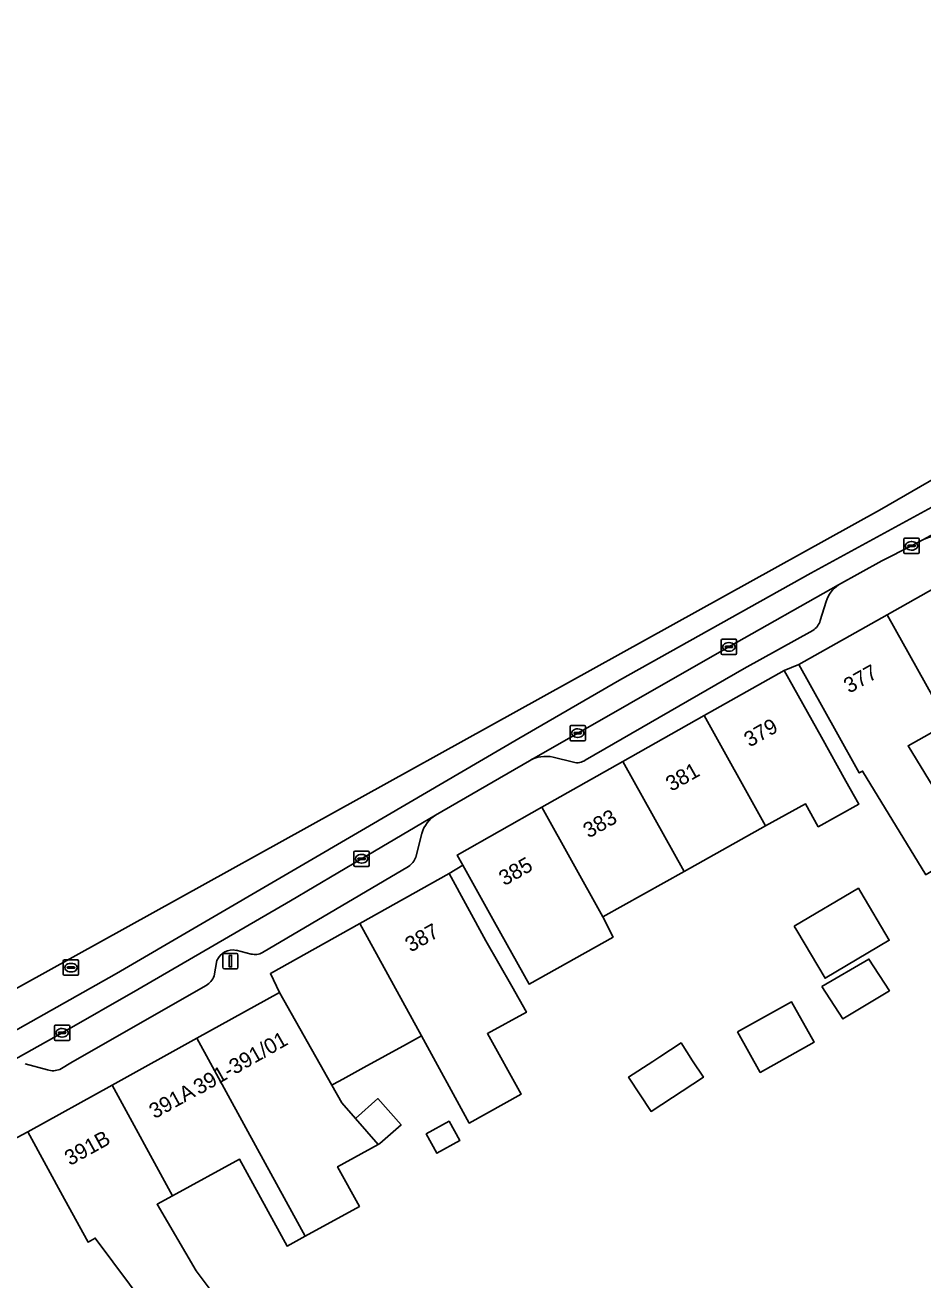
# Model space of a CAD drawing. Extents: x 159817 to 160765, y 380688 to 381638.
# Drawn here: x 159875.5 to 159934.1, y 381436.1 to 381517.9 of the extents above; entities that cross this region are included whole.
import ezdxf

# ---------------------------------------------------------------- set-up
doc = ezdxf.new("R2010")
doc.units = 0
for name, color, linetype in [('IMGEO_Erf', 7, 'Continuous'), ('IMGEO_Kolk', 7, 'Continuous'), ('IMGEO_Lichtmast', 7, 'Continuous'), ('IMGEO_Pand', 7, 'Continuous'), ('IMGEO_Pand_nummerreeks', 7, 'Continuous'), ('IMGEO_Parkeervlak_open', 7, 'Continuous'), ('IMGEO_Rijbaan_lokaal_gesloten', 7, 'Continuous'), ('IMGEO_Rijbaan_lokaal_open', 7, 'Continuous'), ('IMGEO_Rioolput', 7, 'Continuous'), ('IMGEO_Voetpad_open', 7, 'Continuous')]:
    doc.layers.add(name, color=color, linetype=linetype)

msp = doc.modelspace()

# ---------------------------------------------------------------- linework, layer by layer
at = {"layer": 'IMGEO_Erf'}
for points in [[(159934.277, 381462.493), (159930.15, 381469.253), (159929.941, 381469.137), (159928.43, 381471.845), (159925.993, 381476.211), (159925.038, 381475.821), (159927.474, 381471.455), (159929.066, 381468.602), (159929.907, 381467.095), (159927.269, 381465.623), (159926.428, 381467.131), (159923.828, 381465.68), (159918.523, 381462.72), (159913.217, 381459.76), (159913.881, 381458.44), (159908.411, 381455.371), (159906.154, 381459.409), (159904.083, 381463.121), (159903.194, 381462.581), (159905.596, 381458.196), (159907.276, 381455.227), (159908.233, 381453.535), (159905.691, 381452.141), (159907.884, 381448.189), (159904.501, 381446.311), (159901.386, 381451.995), (159900.403, 381451.456), (159897.624, 381449.931), (159896.26, 381449.183), (159895.648, 381448.847), (159895.545, 381448.79), (159896.202, 381447.623), (159897.083, 381446.618), (159898.555, 381447.908), (159900.065, 381446.186), (159898.679, 381444.97), (159898.574, 381444.917), (159895.925, 381443.466), (159897.344, 381440.876), (159893.815, 381438.943), (159892.623, 381438.29), (159889.516, 381443.961), (159885.161, 381441.575), (159884.154, 381441.024), (159886.707, 381436.69), (159891.258, 381430.588)], [(159935.718, 381472.36), (159933.119, 381470.91), (159937.177, 381464.264)], [(159888.044, 381428.191), (159880.12, 381438.814), (159879.651, 381438.557), (159878.123, 381441.346), (159875.721, 381445.731), (159871.093, 381443.281), (159870.548, 381444.237), (159851.506, 381433.392)]]:
    msp.add_lwpolyline(points, dxfattribs=at)
for points in [[(159925.701, 381459.139), (159929.887, 381461.622), (159930.046, 381461.353), (159931.898, 381458.231), (159927.713, 381455.748), (159925.861, 381458.87)], [(159927.501, 381455.219), (159930.567, 381456.998), (159931.907, 381454.941), (159928.877, 381453.102)], [(159921.997, 381452.255), (159925.51, 381454.222), (159926.992, 381451.576), (159923.479, 381449.609)], [(159916.361, 381447.069), (159914.901, 381449.308), (159916.475, 381450.334), (159916.926, 381450.628), (159918.317, 381451.535), (159919.071, 381450.379), (159919.777, 381449.297)], [(159902.399, 381444.344), (159901.7, 381445.604), (159903.192, 381446.432), (159903.891, 381445.172)]]:
    msp.add_lwpolyline(points, close=True, dxfattribs=at)
at = {"layer": 'IMGEO_Kolk'}
for p, q in [((159932.844, 381483.51), (159932.844, 381484.362)), ((159932.919, 381484.436), (159933.771, 381484.436)), ((159933.146, 381483.979), (159933.544, 381483.979)), ((159933.332, 381484.216), (159933.357, 381484.216)), ((159933.845, 381484.362), (159933.845, 381483.51)), ((159933.771, 381483.436), (159932.919, 381483.436)), ((159933.103, 381483.93), (159933.103, 381483.942)), ((159933.541, 381483.893), (159933.143, 381483.893)), ((159933.355, 381483.656), (159933.33, 381483.656)), ((159933.587, 381483.942), (159933.587, 381483.93)), ((159920.935, 381476.921), (159920.935, 381477.773)), ((159921.01, 381477.847), (159921.862, 381477.847)), ((159921.423, 381477.627), (159921.448, 381477.627)), ((159921.936, 381477.773), (159921.936, 381476.921)), ((159921.862, 381476.847), (159921.01, 381476.847)), ((159921.194, 381477.341), (159921.194, 381477.353)), ((159921.632, 381477.304), (159921.234, 381477.304)), ((159921.237, 381477.39), (159921.635, 381477.39)), ((159921.446, 381477.067), (159921.421, 381477.067)), ((159921.678, 381477.353), (159921.678, 381477.341)), ((159911.082, 381471.302), (159911.082, 381472.154)), ((159911.157, 381472.228), (159912.009, 381472.228)), ((159911.341, 381471.722), (159911.341, 381471.734)), ((159911.384, 381471.771), (159911.782, 381471.771)), ((159911.57, 381472.008), (159911.595, 381472.008)), ((159911.825, 381471.734), (159911.825, 381471.722)), ((159912.083, 381472.154), (159912.083, 381471.302)), ((159912.009, 381471.228), (159911.157, 381471.228)), ((159911.779, 381471.685), (159911.381, 381471.685)), ((159911.593, 381471.448), (159911.568, 381471.448)), ((159896.987, 381463.116), (159896.987, 381463.968)), ((159897.062, 381464.042), (159897.914, 381464.042)), ((159897.246, 381463.536), (159897.246, 381463.548)), ((159897.289, 381463.585), (159897.687, 381463.585)), ((159897.475, 381463.822), (159897.5, 381463.822)), ((159897.73, 381463.548), (159897.73, 381463.536)), ((159897.988, 381463.968), (159897.988, 381463.116)), ((159897.914, 381463.042), (159897.062, 381463.042)), ((159897.684, 381463.499), (159897.286, 381463.499)), ((159897.498, 381463.262), (159897.473, 381463.262)), ((159877.457, 381451.769), (159877.457, 381452.621)), ((159877.532, 381452.695), (159878.384, 381452.695)), ((159877.716, 381452.189), (159877.716, 381452.201)), ((159878.154, 381452.152), (159877.756, 381452.152)), ((159877.759, 381452.238), (159878.157, 381452.238)), ((159877.945, 381452.475), (159877.97, 381452.475)), ((159878.2, 381452.201), (159878.2, 381452.189)), ((159878.458, 381452.621), (159878.458, 381451.769)), ((159878.384, 381451.695), (159877.532, 381451.695)), ((159877.968, 381451.915), (159877.943, 381451.915))]:
    msp.add_line(p, q, dxfattribs=at)
for points in [[(159932.844, 381483.51), (159932.844, 381484.362)], [(159932.919, 381484.436), (159933.771, 381484.436)], [(159933.845, 381484.362), (159933.845, 381483.51)], [(159933.771, 381483.436), (159932.919, 381483.436)], [(159920.935, 381476.921), (159920.935, 381477.773)], [(159921.01, 381477.847), (159921.862, 381477.847)], [(159921.936, 381477.773), (159921.936, 381476.921)], [(159921.862, 381476.847), (159921.01, 381476.847)], [(159911.082, 381471.302), (159911.082, 381472.154)], [(159911.157, 381472.228), (159912.009, 381472.228)], [(159912.083, 381472.154), (159912.083, 381471.302)], [(159912.009, 381471.228), (159911.157, 381471.228)], [(159896.987, 381463.116), (159896.987, 381463.968)], [(159897.062, 381464.042), (159897.914, 381464.042)], [(159897.988, 381463.968), (159897.988, 381463.116)], [(159897.914, 381463.042), (159897.062, 381463.042)], [(159877.457, 381451.769), (159877.457, 381452.621)], [(159877.532, 381452.695), (159878.384, 381452.695)], [(159878.458, 381452.621), (159878.458, 381451.769)], [(159878.384, 381451.695), (159877.532, 381451.695)]]:
    msp.add_lwpolyline(points, dxfattribs=at)
for centre, radius, start, end in [((159932.921, 381484.36), 0.0765, 91.55205, 178.44795), ((159932.921, 381484.36), 0.0765, 91.55205, 178.44795), ((159933.143, 381483.939), 0.0403, 85.87752, 175.75265), ((159933.548, 381483.941), 0.0386, 1.73085, 96.63898), ((159933.769, 381484.36), 0.0765, 1.55205, 88.44795), ((159933.769, 381484.36), 0.0765, 1.55205, 88.44795), ((159932.921, 381483.512), 0.0765, 181.55205, 268.44795), ((159932.921, 381483.512), 0.0765, 181.55205, 268.44795), ((159933.14, 381483.929), 0.0366, 178.93798, 274.71019), ((159933.544, 381483.936), 0.043, 264.86636, 352.45326), ((159933.769, 381483.512), 0.0765, 271.55205, 358.44795), ((159933.769, 381483.512), 0.0765, 271.55205, 358.44795), ((159921.012, 381477.771), 0.0765, 91.55205, 178.44795), ((159921.012, 381477.771), 0.0765, 91.55205, 178.44795), ((159921.86, 381477.771), 0.0765, 1.55205, 88.44795), ((159921.86, 381477.771), 0.0765, 1.55205, 88.44795), ((159921.012, 381476.923), 0.0765, 181.55205, 268.44795), ((159921.012, 381476.923), 0.0765, 181.55205, 268.44795), ((159921.234, 381477.35), 0.0403, 85.87752, 175.75265), ((159921.231, 381477.34), 0.0366, 178.93798, 274.71019), ((159921.635, 381477.347), 0.043, 264.86636, 352.45326), ((159921.639, 381477.352), 0.0386, 1.73085, 96.63898), ((159921.86, 381476.923), 0.0765, 271.55205, 358.44795), ((159921.86, 381476.923), 0.0765, 271.55205, 358.44795), ((159911.159, 381472.152), 0.0765, 91.55205, 178.44795), ((159911.159, 381472.152), 0.0765, 91.55205, 178.44795), ((159911.381, 381471.731), 0.0403, 85.87752, 175.75265), ((159911.378, 381471.721), 0.0366, 178.93798, 274.71019), ((159911.782, 381471.728), 0.043, 264.86636, 352.45326), ((159911.786, 381471.733), 0.0386, 1.73085, 96.63898), ((159912.007, 381472.152), 0.0765, 1.55205, 88.44795), ((159912.007, 381472.152), 0.0765, 1.55205, 88.44795), ((159911.159, 381471.304), 0.0765, 181.55205, 268.44795), ((159911.159, 381471.304), 0.0765, 181.55205, 268.44795), ((159912.007, 381471.304), 0.0765, 271.55205, 358.44795), ((159912.007, 381471.304), 0.0765, 271.55205, 358.44795), ((159897.064, 381463.966), 0.0765, 91.55205, 178.44795), ((159897.064, 381463.966), 0.0765, 91.55205, 178.44795), ((159897.286, 381463.545), 0.0403, 85.87752, 175.75265), ((159897.283, 381463.535), 0.0366, 178.93798, 274.71019), ((159897.687, 381463.542), 0.043, 264.86636, 352.45326), ((159897.691, 381463.547), 0.0386, 1.73085, 96.63898), ((159897.912, 381463.966), 0.0765, 1.55205, 88.44795), ((159897.912, 381463.966), 0.0765, 1.55205, 88.44795), ((159897.064, 381463.118), 0.0765, 181.55205, 268.44795), ((159897.064, 381463.118), 0.0765, 181.55205, 268.44795), ((159897.912, 381463.118), 0.0765, 271.55205, 358.44795), ((159897.912, 381463.118), 0.0765, 271.55205, 358.44795), ((159877.534, 381452.619), 0.0765, 91.55205, 178.44795), ((159877.534, 381452.619), 0.0765, 91.55205, 178.44795), ((159877.756, 381452.198), 0.0403, 85.87752, 175.75265), ((159877.753, 381452.188), 0.0366, 178.93798, 274.71019), ((159878.157, 381452.195), 0.043, 264.86636, 352.45326), ((159878.161, 381452.2), 0.0386, 1.73085, 96.63898), ((159878.382, 381452.619), 0.0765, 1.55205, 88.44795), ((159878.382, 381452.619), 0.0765, 1.55205, 88.44795), ((159877.534, 381451.771), 0.0765, 181.55205, 268.44795), ((159877.534, 381451.771), 0.0765, 181.55205, 268.44795), ((159878.382, 381451.771), 0.0765, 271.55205, 358.44795), ((159878.382, 381451.771), 0.0765, 271.55205, 358.44795)]:
    msp.add_arc(centre, radius, start, end, dxfattribs=at)
for centre, major_axis, ratio, start_param, end_param in [((159933.331, 381483.936), (-0.387, 0.002), 0.722429, 4.712389, 7.853982), ((159933.356, 381483.936), (-0.39, 0.002), 0.717154, 1.570796, 4.712389), ((159921.422, 381477.347), (-0.387, 0.002), 0.722429, 4.712389, 7.853982), ((159921.447, 381477.347), (-0.39, 0.002), 0.717154, 1.570796, 4.712389), ((159911.569, 381471.728), (-0.387, 0.002), 0.722429, 4.712389, 7.853982), ((159911.594, 381471.728), (-0.39, 0.002), 0.717154, 1.570796, 4.712389), ((159897.474, 381463.542), (-0.387, 0.002), 0.722429, 4.712389, 7.853982), ((159897.499, 381463.542), (-0.39, 0.002), 0.717154, 1.570796, 4.712389), ((159877.944, 381452.195), (-0.387, 0.002), 0.722429, 4.712389, 7.853982), ((159877.969, 381452.195), (-0.39, 0.002), 0.717154, 1.570796, 4.712389)]:
    msp.add_ellipse(centre, major_axis=major_axis, ratio=ratio, start_param=start_param, end_param=end_param, dxfattribs=at)
at = {"layer": 'IMGEO_Lichtmast'}
for p, q in [((159888.436, 381456.464), (159888.436, 381457.264)), ((159888.436, 381457.264), (159888.436, 381456.464)), ((159888.536, 381457.364), (159889.326, 381457.364)), ((159889.326, 381457.364), (159888.536, 381457.364)), ((159889.426, 381457.264), (159889.426, 381456.464)), ((159889.426, 381456.464), (159889.426, 381457.264)), ((159889.326, 381456.364), (159888.536, 381456.364)), ((159888.536, 381456.364), (159889.326, 381456.364))]:
    msp.add_line(p, q, dxfattribs=at)
msp.add_lwpolyline([(159888.856, 381457.239), (159889.006, 381457.239), (159889.006, 381456.489), (159888.856, 381456.489), (159888.856, 381457.239)], dxfattribs=at)
for centre, start, end in [((159888.536, 381457.264), 90, 180), ((159888.536, 381457.264), 90, 180), ((159889.326, 381457.264), 0, 90), ((159889.326, 381457.264), 360, 90), ((159888.536, 381456.464), 180, 270), ((159888.536, 381456.464), 180, 270), ((159889.326, 381456.464), 270, 0), ((159889.326, 381456.464), 270, 0)]:
    msp.add_arc(centre, 0.1, start, end, dxfattribs=at)
at = {"layer": 'IMGEO_Pand'}
for points in [[(159931.762, 381479.45), (159935.718, 381472.36), (159937.807, 381468.81), (159939.859, 381465.323), (159941.709, 381466.023), (159944.571, 381467.579), (159945.046, 381466.705), (159945.986, 381467.216), (159937.151, 381482.476)], [(159933.119, 381470.91), (159935.718, 381472.36), (159931.762, 381479.45), (159925.993, 381476.211), (159928.43, 381471.845), (159929.941, 381469.137), (159930.15, 381469.253), (159934.277, 381462.493), (159934.303, 381462.509), (159936.71, 381463.979), (159937.177, 381464.264)], [(159923.828, 381465.68), (159926.428, 381467.131), (159927.269, 381465.623), (159929.907, 381467.095), (159929.066, 381468.602), (159927.474, 381471.455), (159925.038, 381475.821), (159919.814, 381472.869)], [(159923.828, 381465.68), (159919.814, 381472.869), (159914.526, 381469.882), (159918.523, 381462.72)], [(159909.236, 381466.893), (159913.217, 381459.76), (159918.523, 381462.72), (159914.526, 381469.882)], [(159909.236, 381466.893), (159903.718, 381463.775), (159904.083, 381463.121), (159906.154, 381459.409), (159908.411, 381455.371), (159913.881, 381458.44), (159913.217, 381459.76)], [(159907.276, 381455.227), (159905.596, 381458.196), (159903.194, 381462.581), (159897.371, 381459.323), (159901.386, 381451.995), (159904.501, 381446.311), (159907.884, 381448.189), (159905.691, 381452.141), (159908.233, 381453.535)], [(159925.701, 381459.139), (159925.861, 381458.87), (159927.713, 381455.748), (159931.898, 381458.231), (159930.046, 381461.353), (159929.887, 381461.622)], [(159900.403, 381451.456), (159901.386, 381451.995), (159897.371, 381459.323), (159891.539, 381456.059), (159892.143, 381454.829), (159895.545, 381448.79), (159895.648, 381448.847), (159896.26, 381449.183), (159897.624, 381449.931)], [(159927.501, 381455.219), (159928.877, 381453.102), (159931.907, 381454.941), (159930.567, 381456.998)], [(159896.202, 381447.623), (159895.545, 381448.79), (159892.143, 381454.829), (159886.749, 381451.841), (159890.708, 381444.614), (159893.815, 381438.943), (159897.344, 381440.876), (159895.925, 381443.466), (159898.574, 381444.917), (159897.083, 381446.618)], [(159921.997, 381452.255), (159923.479, 381449.609), (159926.992, 381451.576), (159925.51, 381454.222)], [(159885.161, 381441.575), (159889.516, 381443.961), (159892.623, 381438.29), (159893.815, 381438.943), (159890.708, 381444.614), (159886.749, 381451.841), (159881.217, 381448.776)], [(159919.071, 381450.379), (159918.317, 381451.535), (159916.926, 381450.628), (159916.475, 381450.334), (159914.901, 381449.308), (159916.361, 381447.069), (159919.777, 381449.297)], [(159885.161, 381441.575), (159881.217, 381448.776), (159875.721, 381445.731), (159878.123, 381441.346), (159879.651, 381438.557), (159880.12, 381438.814), (159888.044, 381428.191), (159891.258, 381430.588), (159886.707, 381436.69), (159884.154, 381441.024)], [(159897.083, 381446.618), (159898.574, 381444.917), (159898.679, 381444.97), (159900.065, 381446.186), (159898.555, 381447.908)], [(159901.7, 381445.604), (159902.399, 381444.344), (159903.891, 381445.172), (159903.192, 381446.432)]]:
    msp.add_lwpolyline(points, close=True, dxfattribs=at)
at = {"layer": 'IMGEO_Parkeervlak_open'}
for points in [[(159942.338, 381488.805), (159934.089, 381484.332)], [(159928.594, 381481.394), (159921.431, 381477.348), (159908.426, 381469.932)], [(159927.394, 381479.063), (159927.783, 381480.309)], [(159912.073, 381469.965), (159922.433, 381475.938), (159926.902, 381478.419)], [(159909.975, 381470.161), (159911.298, 381469.828)], [(159902.312, 381466.385), (159897.484, 381463.543), (159892.858, 381460.807), (159882.894, 381455.01), (159877.954, 381452.196), (159874.01, 381449.972)], [(159901.013, 381463.64), (159901.418, 381465.193)], [(159891.024, 381457.431), (159900.548, 381463.034)], [(159889.31, 381457.571), (159890.282, 381457.331)], [(159887.88, 381455.901), (159888.055, 381456.912)], [(159877.808, 381449.813), (159878.625, 381450.304), (159887.348, 381455.276)], [(159875.542, 381450.165), (159877, 381449.775)]]:
    msp.add_lwpolyline(points, dxfattribs=at)
for centre, radius, start, end in [((159934.963, 381482.687), 1.863, 69.41928, 117.98998), ((159929.652, 381479.758), 1.949, 122.88298, 163.56333), ((159926.281, 381479.404), 1.164, 302.25097, 342.99117), ((159909.499, 381468.029), 2.185, 77.41008, 119.409), ((159911.532, 381470.765), 0.966, 255.99091, 304.05879), ((159903.363, 381464.666), 2.015, 121.42865, 164.83155), ((159899.878, 381464.029), 1.2, 303.94045, 341.05957), ((159889.08, 381456.485), 1.11, 78.03815, 157.36974), ((159890.529, 381458.3), 1, 255.69812, 299.65299), ((159886.58, 381456.469), 1.419, 302.78688, 336.40426), ((159877.349, 381450.96), 1.236, 253.5866, 291.79864)]:
    msp.add_arc(centre, radius, start, end, dxfattribs=at)
at = {"layer": 'IMGEO_Rijbaan_lokaal_gesloten'}
msp.add_lwpolyline([(159824.612, 381427.213), (159825.741, 381425.114), (159830.92, 381427.938), (159857.238, 381442.392), (159881.509, 381456.068), (159898.004, 381465.69), (159907.745, 381471.382), (159914.294, 381475.19), (159926.777, 381482.151), (159943.271, 381491.16), (159954.568, 381497.138), (159968.238, 381504.058), (159981.458, 381511.387), (159987.706, 381515.056), (159986.055, 381517.88), (159931.265, 381486.272)], close=True, dxfattribs=at)
at = {"layer": 'IMGEO_Rijbaan_lokaal_open'}
for points in [[(159943.271, 381491.16), (159926.777, 381482.151), (159914.294, 381475.19), (159907.745, 381471.382), (159898.004, 381465.69), (159881.509, 381456.068), (159857.238, 381442.392), (159830.92, 381427.938)], [(159827.8, 381424.443), (159868.202, 381446.726), (159868.305, 381446.783), (159874.01, 381449.972), (159877.954, 381452.196), (159882.894, 381455.01), (159892.858, 381460.807), (159897.484, 381463.543), (159902.312, 381466.385), (159908.426, 381469.932), (159921.431, 381477.348), (159928.594, 381481.394), (159931.412, 381482.953), (159933.344, 381483.936), (159934.089, 381484.332), (159942.338, 381488.805)]]:
    msp.add_lwpolyline(points, dxfattribs=at)
at = {"layer": 'IMGEO_Rioolput'}
for p, q in [((159878.034, 381456.017), (159878.034, 381456.869)), ((159878.109, 381456.943), (159878.961, 381456.943)), ((159878.293, 381456.437), (159878.293, 381456.449)), ((159878.731, 381456.4), (159878.333, 381456.4)), ((159878.336, 381456.486), (159878.734, 381456.486)), ((159878.545, 381456.163), (159878.52, 381456.163)), ((159878.522, 381456.723), (159878.547, 381456.723)), ((159878.777, 381456.449), (159878.777, 381456.437)), ((159879.035, 381456.869), (159879.035, 381456.017)), ((159878.961, 381455.943), (159878.109, 381455.943))]:
    msp.add_line(p, q, dxfattribs=at)
for points in [[(159878.034, 381456.017), (159878.034, 381456.869)], [(159878.109, 381456.943), (159878.961, 381456.943)], [(159879.035, 381456.869), (159879.035, 381456.017)], [(159878.961, 381455.943), (159878.109, 381455.943)]]:
    msp.add_lwpolyline(points, dxfattribs=at)
for centre, radius, start, end in [((159878.111, 381456.867), 0.0765, 91.55205, 178.44795), ((159878.111, 381456.867), 0.0765, 91.55205, 178.44795), ((159878.333, 381456.446), 0.0403, 85.87752, 175.75265), ((159878.33, 381456.436), 0.0366, 178.93798, 274.71019), ((159878.734, 381456.443), 0.043, 264.86636, 352.45326), ((159878.738, 381456.448), 0.0386, 1.73085, 96.63898), ((159878.959, 381456.867), 0.0765, 1.55205, 88.44795), ((159878.959, 381456.867), 0.0765, 1.55205, 88.44795), ((159878.111, 381456.019), 0.0765, 181.55205, 268.44795), ((159878.111, 381456.019), 0.0765, 181.55205, 268.44795), ((159878.959, 381456.019), 0.0765, 271.55205, 358.44795), ((159878.959, 381456.019), 0.0765, 271.55205, 358.44795)]:
    msp.add_arc(centre, radius, start, end, dxfattribs=at)
for centre, major_axis, ratio, start_param, end_param in [((159878.521, 381456.443), (-0.387, 0.002), 0.722429, 4.712389, 7.853982), ((159878.546, 381456.443), (-0.39, 0.002), 0.717154, 1.570796, 4.712389)]:
    msp.add_ellipse(centre, major_axis=major_axis, ratio=ratio, start_param=start_param, end_param=end_param, dxfattribs=at)
at = {"layer": 'IMGEO_Voetpad_open'}
for points in [[(159934.089, 381484.332), (159933.344, 381483.936), (159931.412, 381482.953), (159928.594, 381481.394)], [(159851.506, 381433.392), (159870.548, 381444.237), (159871.093, 381443.281), (159875.721, 381445.731), (159881.217, 381448.776), (159886.749, 381451.841), (159892.143, 381454.829), (159891.539, 381456.059), (159897.371, 381459.323), (159903.194, 381462.581), (159904.083, 381463.121), (159903.718, 381463.775), (159909.236, 381466.893), (159914.526, 381469.882), (159919.814, 381472.869), (159925.038, 381475.821), (159925.993, 381476.211), (159931.762, 381479.45), (159937.151, 381482.476)], [(159927.783, 381480.309), (159927.394, 381479.063)], [(159926.902, 381478.419), (159922.433, 381475.938), (159912.073, 381469.965)], [(159911.298, 381469.828), (159909.975, 381470.161)], [(159908.426, 381469.932), (159902.312, 381466.385)], [(159901.418, 381465.193), (159901.013, 381463.64)], [(159900.548, 381463.034), (159891.024, 381457.431)], [(159890.282, 381457.331), (159889.31, 381457.571)], [(159888.055, 381456.912), (159887.88, 381455.901)], [(159887.348, 381455.276), (159878.625, 381450.304), (159877.808, 381449.813)], [(159877, 381449.775), (159875.542, 381450.165)]]:
    msp.add_lwpolyline(points, dxfattribs=at)
for centre, radius, start, end in [((159934.963, 381482.687), 1.863, 69.41928, 117.98998), ((159929.652, 381479.758), 1.949, 122.88298, 163.56333), ((159926.281, 381479.404), 1.164, 302.25097, 342.99117), ((159909.499, 381468.029), 2.185, 77.41008, 119.409), ((159911.532, 381470.765), 0.966, 255.99091, 304.05879), ((159903.363, 381464.666), 2.015, 121.42865, 164.83155), ((159899.878, 381464.029), 1.2, 303.94045, 341.05957), ((159889.08, 381456.485), 1.11, 78.03815, 157.36974), ((159890.529, 381458.3), 1, 255.69812, 299.65299), ((159886.58, 381456.469), 1.419, 302.78688, 336.40426), ((159877.349, 381450.96), 1.236, 253.5866, 291.79864)]:
    msp.add_arc(centre, radius, start, end, dxfattribs=at)

# ---------------------------------------------------------------- texts
at = {"layer": 'IMGEO_Pand_nummerreeks'}
for s, rotation, p in [('377', 29.31252, (159929.281, 381474.295)), ('379', 29.46686, (159922.786, 381470.781)), ('381', 29.46686, (159917.682, 381467.897)), ('383', 29.46686, (159912.294, 381464.853)), ('385', 29.46686, (159906.796, 381461.747)), ('387', 29.22658, (159900.681, 381457.417)), ('391-391/01', 29.62192, (159886.882, 381448.125)), ('391A', 28.98861, (159883.982, 381446.559)), ('391B', 28.98818, (159878.468, 381443.504))]:
    msp.add_text(s, height=1, rotation=rotation, dxfattribs=at).set_placement(p)

doc.saveas('drawing.dxf')
